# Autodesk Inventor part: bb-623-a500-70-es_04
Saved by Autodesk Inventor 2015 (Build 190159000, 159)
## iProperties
Created: 2022-04
Part Number: bb-623-a500-70-es_04
Checked By: TraceParts S.A.
Material: Generic
Catalog Web Link: www.traceparts.com
Document SubType Name: Modeling
Designer: TraceParts
Density: 1 g/cm^3
Appearance: Default
Company: TraceParts S.A.
Author: TraceParts
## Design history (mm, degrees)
feature "bb-623-a500-70-es_04.ipt"
body "Solid1"
